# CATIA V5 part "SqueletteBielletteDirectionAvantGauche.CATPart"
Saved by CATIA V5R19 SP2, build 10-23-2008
Part number: SqueletteBielletteDirectionAvantGauche
Bounding box of the stored display mesh (mm): x 0 to 54.161, y 0 to 0, z 0 to 0
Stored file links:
  E:\Mes documents\03_Ressources pédagogiques\01_Catia\Buggy Dassault\SchemaCinematiqueFinal\SqueletteBielletteDirectionAvantGauche.CATPart
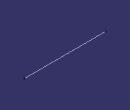
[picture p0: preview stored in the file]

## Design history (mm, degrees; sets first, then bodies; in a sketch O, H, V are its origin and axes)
AxisSystem1: origin (0, 0, 0), X (1, 0, 0), Y (0, 1, 0), Z (0, 0, 1)
Set1
  Line1: type PtDir, RefPoint vertex [YZ plane of AxisSystem1 | ZX plane of AxisSystem1 | XY plane of AxisSystem1], Direction edge [XY plane of AxisSystem1 | ZX plane of AxisSystem1], Start 0, End 54.161
Body1 (main body)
